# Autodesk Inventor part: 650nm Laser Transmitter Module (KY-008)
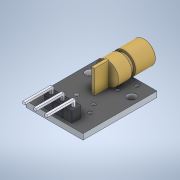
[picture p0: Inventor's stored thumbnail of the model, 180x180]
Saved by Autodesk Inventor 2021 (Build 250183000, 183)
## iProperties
Created: 2019-10
Part Number: 650nm Laser Transmitter Module (KY-008)
Material: Generic
Description: STEP AP214
Document SubType Name: Modeling
Designer: alolo
Density: 1 g/cm^3
Appearance: Default
Title: 650nm Laser Transmitter Module (KY-008).STEP
Revision Number: ANY
Sending System: SolidWorks 2018
Preprocessor: SwSTEP 2.0
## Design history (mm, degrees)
fillet "Fillet5"
body "Solid1"
